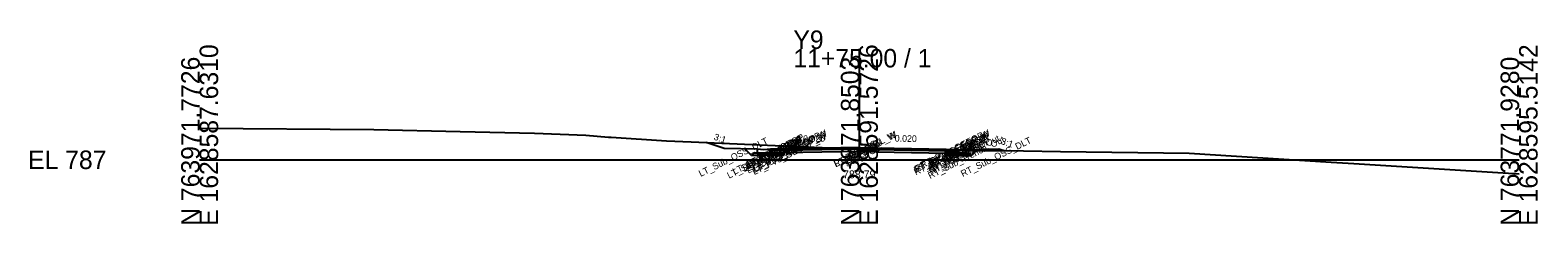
# Model space of a CAD drawing. Extents: x -26 to 203, y -10 to 6017.
# Drawn here: x -25.7 to 202.8, y 3490.3 to 3519.6 of the extents above; entities that cross this region are included whole.
import ezdxf

# ---------------------------------------------------------------- set-up
doc = ezdxf.new("R2010")
doc.units = 0
for name, color, linetype in [('Default', 7, 'Continuous'), ('Exist Cross Section Cell', 7, 'Continuous'), ('Exist XS Center Line Elevation Label', 7, 'Continuous'), ('Exist XS Ground Line', 7, 'Continuous'), ('Prop CMT Concrete Structures', 7, 'Continuous'), ('Prop CMT Pvmt Course 1', 7, 'Continuous'), ('Prop CMT Pvmt Course 1 Wedge', 7, 'Continuous'), ('Prop CMT Pvmt Course 2', 7, 'Continuous'), ('Prop CMT Pvmt Course 3', 7, 'Continuous'), ('Prop CMT Pvmt Surface', 7, 'Continuous'), ('Prop CMT Pvmt Surface Shoulder', 7, 'Continuous'), ('Prop CMT Pvmt Wedge Surface 1', 7, 'Continuous'), ('Prop CMT Pvmt Wedge Surface 2', 7, 'Continuous'), ('Prop CMT Pvmt Wedge Surface 3', 7, 'Continuous'), ('Prop CMT Shld Paved Course 1', 7, 'Continuous'), ('Prop CMT Shld Paved Course 2', 7, 'Continuous'), ('Prop CMT Shld Paved Course 3', 7, 'Continuous'), ('Prop CMT Slope Grass', 7, 'Continuous'), ('Prop CMT Subgrade Earthwork', 7, 'Continuous'), ('Prop XS SE Text', 7, 'Continuous'), ('Prop XS Side Slope Text', 7, 'Continuous'), ('Scratch_Level_0', 7, 'Continuous')]:
    doc.layers.add(name, color=color, linetype=linetype)

msp = doc.modelspace()

# ---------------------------------------------------------------- linework, layer by layer
at = {"layer": 'Exist Cross Section Cell'}
for p, q in [((100, 3500), (100, 3516.78)), ((0, 3500), (100, 3500)), ((100, 3500), (200, 3500))]:
    msp.add_line(p, q, dxfattribs=at)
at = {"layer": 'Exist XS Ground Line'}
msp.add_lwpolyline([(0, 3504.79), (26.41, 3504.61), (39.51, 3504.29), (50.77, 3504.01), (58.56, 3503.71), (60.26, 3503.58), (61.99, 3503.44), (62.36, 3503.42), (70.77, 3502.88), (74.49, 3502.7), (89.55, 3502.07), (94.34, 3501.85), (96.44, 3501.79), (98.74, 3501.81), (100, 3501.79), (101.48, 3501.77), (115.89, 3501.4), (124.9, 3501.35), (130.49, 3501.27), (149.97, 3500.99), (171.51, 3499.66), (174.97, 3499.45), (200, 3497.85)], dxfattribs=at)
at = {"layer": 'Prop CMT Concrete Structures'}
for points in [[(84.51, 3501.6), (84.51, 3501.01), (86.51, 3501.01)], [(86.51, 3501.6), (85.51, 3501.51), (84.51, 3501.6)], [(86.51, 3501.01), (86.51, 3501.6)], [(116.16, 3501.58), (116.16, 3501), (114.16, 3501)], [(114.16, 3501.58), (115.16, 3501.5), (116.16, 3501.58)], [(114.16, 3501), (114.16, 3501.58)]]:
    msp.add_lwpolyline(points, dxfattribs=at)
at = {"layer": 'Prop CMT Pvmt Course 1'}
for points in [[(100, 3501.87), (86.51, 3501.6)], [(86.51, 3501.6), (86.51, 3501.35)], [(86.51, 3501.35), (88.6, 3501.39)], [(100, 3501.87), (88.6, 3501.64)], [(88.6, 3501.64), (88.6, 3501.51)], [(100, 3501.74), (100, 3501.87)], [(100, 3501.62), (100, 3501.87)], [(100, 3501.87), (113.16, 3501.6)], [(100, 3501.74), (100, 3501.87)], [(100, 3501.87), (114.16, 3501.58)], [(100, 3501.62), (100, 3501.87)], [(113.16, 3501.48), (100, 3501.74)], [(113.16, 3501.6), (113.16, 3501.48)], [(114.16, 3501.33), (113.16, 3501.35)], [(114.16, 3501.58), (114.16, 3501.33)]]:
    msp.add_lwpolyline(points, dxfattribs=at)
at = {"layer": 'Prop CMT Pvmt Course 1 Wedge'}
for points in [[(113.16, 3501.47), (111.41, 3501.51)], [(111.41, 3501.51), (113.16, 3501.48)], [(113.16, 3501.48), (113.16, 3501.47)]]:
    msp.add_lwpolyline(points, dxfattribs=at)
at = {"layer": 'Prop CMT Pvmt Course 2'}
for points in [[(88.6, 3501.39), (86.51, 3501.35)], [(86.51, 3501.35), (86.51, 3501.01)], [(113.16, 3501.35), (114.16, 3501.33)], [(114.16, 3501.33), (114.16, 3501)], [(86.51, 3501.01), (88.6, 3501.05)], [(114.16, 3501), (113.16, 3501.02)]]:
    msp.add_lwpolyline(points, dxfattribs=at)
at = {"layer": 'Prop CMT Pvmt Course 3'}
msp.add_line((116.16, 3501), (116.66, 3501), dxfattribs=at)
for points in [[(88.6, 3501.05), (86.51, 3501.01)], [(86.51, 3501.01), (86.51, 3500.68)], [(86.51, 3500.68), (88.6, 3500.72)], [(113.16, 3501.02), (114.16, 3501)], [(114.16, 3500.67), (113.16, 3500.69)], [(114.16, 3501), (114.16, 3500.67)]]:
    msp.add_lwpolyline(points, dxfattribs=at)
at = {"layer": 'Prop CMT Pvmt Surface'}
for points in [[(100, 3501.87), (86.51, 3501.6)], [(100, 3501.87), (88.6, 3501.64)], [(100, 3501.87), (114.16, 3501.58)], [(100, 3501.87), (113.16, 3501.6)]]:
    msp.add_lwpolyline(points, dxfattribs=at)
at = {"layer": 'Prop CMT Pvmt Surface Shoulder'}
for points in [[(86.51, 3501.6), (86.51, 3501.6)], [(114.16, 3501.58), (114.16, 3501.58)]]:
    msp.add_lwpolyline(points, dxfattribs=at)
at = {"layer": 'Prop CMT Pvmt Wedge Surface 1'}
for points in [[(88.6, 3501.51), (88.6, 3501.64)], [(100, 3501.74), (113.16, 3501.48)], [(113.16, 3501.48), (113.16, 3501.6)]]:
    msp.add_lwpolyline(points, dxfattribs=at)
at = {"layer": 'Prop CMT Pvmt Wedge Surface 2'}
for points in [[(88.6, 3501.39), (88.6, 3501.64)], [(100, 3501.62), (88.6, 3501.39)], [(100, 3501.62), (100, 3501.87)], [(100, 3501.62), (100, 3501.87)], [(100, 3501.62), (100, 3501.87)], [(100, 3501.62), (100, 3501.87)], [(100, 3501.62), (113.16, 3501.35)], [(113.16, 3501.35), (113.16, 3501.6)]]:
    msp.add_lwpolyline(points, dxfattribs=at)
at = {"layer": 'Prop CMT Pvmt Wedge Surface 3'}
for points in [[(88.6, 3501.05), (88.6, 3501.64)], [(100, 3501.28), (88.6, 3501.05)], [(100, 3501.28), (100, 3501.87)], [(100, 3501.28), (113.16, 3501.02)], [(113.16, 3501.02), (113.16, 3501.6)]]:
    msp.add_lwpolyline(points, dxfattribs=at)
at = {"layer": 'Prop CMT Shld Paved Course 1'}
for points in [[(86.51, 3501.6), (86.51, 3501.6)], [(86.51, 3501.35), (86.51, 3501.6)], [(114.16, 3501.58), (114.16, 3501.58)], [(114.16, 3501.33), (114.16, 3501.58)]]:
    msp.add_lwpolyline(points, dxfattribs=at)
at = {"layer": 'Prop CMT Shld Paved Course 2'}
for p, q in [((84.51, 3501.01), (86.51, 3501.01)), ((116.16, 3501), (114.16, 3501))]:
    msp.add_line(p, q, dxfattribs=at)
for points in [[(86.51, 3501.01), (86.51, 3501.35)], [(114.16, 3501), (114.16, 3501.33)]]:
    msp.add_lwpolyline(points, dxfattribs=at)
at = {"layer": 'Prop CMT Shld Paved Course 3'}
for p, q in [((83.67, 3500.67), (86.51, 3500.68)), ((117, 3500.66), (114.16, 3500.67))]:
    msp.add_line(p, q, dxfattribs=at)
for points in [[(86.51, 3501.01), (84.51, 3501.01), (84.01, 3501.01), (83.67, 3500.67)], [(86.51, 3500.68), (86.51, 3501.01)], [(114.16, 3500.67), (114.16, 3501)], [(114.16, 3501), (116.66, 3501), (116.66, 3501), (117, 3500.66)]]:
    msp.add_lwpolyline(points, dxfattribs=at)
at = {"layer": 'Prop CMT Slope Grass'}
for points in [[(84.51, 3501.6), (79.51, 3501.7), (76.78, 3502.61)], [(116.16, 3501.58), (121.16, 3501.68), (122.11, 3501.37)]]:
    msp.add_lwpolyline(points, dxfattribs=at)
at = {"layer": 'Prop CMT Subgrade Earthwork'}
for p, q in [((83.67, 3500.67), (82.71, 3501.63)), ((88.6, 3500.72), (88.6, 3501.64)), ((113.16, 3500.69), (113.16, 3501.47)), ((117, 3500.66), (117.96, 3501.62)), ((86.51, 3500.68), (83.67, 3500.67)), ((114.16, 3500.67), (117, 3500.66))]:
    msp.add_line(p, q, dxfattribs=at)
for points in [[(88.6, 3500.72), (86.51, 3500.68)], [(113.16, 3500.69), (114.16, 3500.67)]]:
    msp.add_lwpolyline(points, dxfattribs=at)

# ---------------------------------------------------------------- texts
at = {"layer": 'Default'}
msp.add_text('-', height=0.0001, dxfattribs=at).set_placement((0, 3500))
at = {"layer": 'Exist Cross Section Cell'}
for s, p in [('Y9', (90, 3516.78)), ('11+75.00 / 1', (90, 3513.98)), ('EL 787', (-26, 3498.6))]:
    msp.add_text(s, height=2.8, dxfattribs=at).set_placement(p)
for s, p in [('E 1628587.6310', (2.8, 3490)), ('E 1628591.5726', (102.8, 3490)), ('E 1628595.5142', (202.8, 3490)), ('N 763971.7726', (0, 3490)), ('N 763871.8503', (100, 3490)), ('N 763771.9280', (200, 3490))]:
    msp.add_text(s, height=2.8, rotation=90, dxfattribs=at).set_placement(p)
at = {"layer": 'Exist XS Center Line Elevation Label'}
msp.add_text('788.79', height=1.2, dxfattribs=at).set_placement((97.52, 3497.19))
at = {"layer": 'Prop XS SE Text'}
for rotation, p in [(1.1458, (91.48, 3502.7)), (358.8542, (105.35, 3502.76))]:
    msp.add_text('0.020', height=1, rotation=rotation, dxfattribs=at).set_placement(p)
at = {"layer": 'Prop XS Side Slope Text'}
for p in [(77.85, 3503.07), (121.37, 3502.41)]:
    msp.add_text('3:1', height=1, rotation=341.5651, dxfattribs=at).set_placement(p)
at = {"layer": 'Scratch_Level_0'}
for s, p in [('LT_Sub_OSS_DLT', (75.95, 3497.39)), ('LT_Sub_Trench_Out', (80.25, 3497.12)), ('LT_PS3_Shelf_Out', (81.08, 3497.71)), ('LT_PS2_OEOP', (82.93, 3498.56)), ('LT_PV2_OEOT', (83.15, 3498.55)), ('LT_PV1_OEOT', (83.26, 3498.85)), ('LT_PS1_OEOP', (83.29, 3498.87)), ('LT_PV2_OEEOP_W', (84.07, 3498)), ('LT_PV3_OEEOP_W', (84.07, 3497.67)), ('LT_PV1_OEEOP_W', (84.18, 3498.18)), ('LT_PV1_OEEOP', (85.04, 3498.74)), ('RT_PV1_PGL_W', (96.41, 3498.83)), ('LT_PV1_PGL_W', (96.47, 3498.86)), ('RT_PV2_OEEOP_W', (108.57, 3497.94)), ('RT_PV3_OEEOP_W', (108.57, 3497.61)), ('RT_PV1_OEEOP_W', (108.68, 3498.12)), ('RT_PV1_OEEOP', (109.54, 3498.68)), ('RT_Sub_Trench_Out', (110.72, 3497.08)), ('RT_PV2_OEOT', (110.75, 3498.51)), ('RT_PV1_OEOT', (110.85, 3498.81)), ('RT_PS3_Shelf_Out', (110.87, 3497.67)), ('RT_PS1_OEOP', (110.89, 3498.83)), ('RT_PS2_OEOP', (111.04, 3498.52)), ('RT_Sub_OSS_DLT', (115.68, 3497.37)), ('LT_PS3_OEOP', (82.59, 3498.22)), ('LT_PV3_OEOT', (83.15, 3498.22)), ('LT_Sub_OEOT', (83.17, 3497.89)), ('PV2_PGL', (98.08, 3499.54)), ('PV3_PGL', (98.08, 3499.2)), ('Sub_PGL', (98.1, 3498.88)), ('PV1_PGL', (98.18, 3499.84)), ('RT_PV3_OEOT', (110.75, 3498.18)), ('RT_Sub_OEOT', (110.77, 3497.85)), ('RT_PS3_OEOP', (111.38, 3498.18))]:
    msp.add_text(s, height=1, rotation=26.5651, dxfattribs=at).set_placement(p)

doc.saveas('drawing.dxf')
